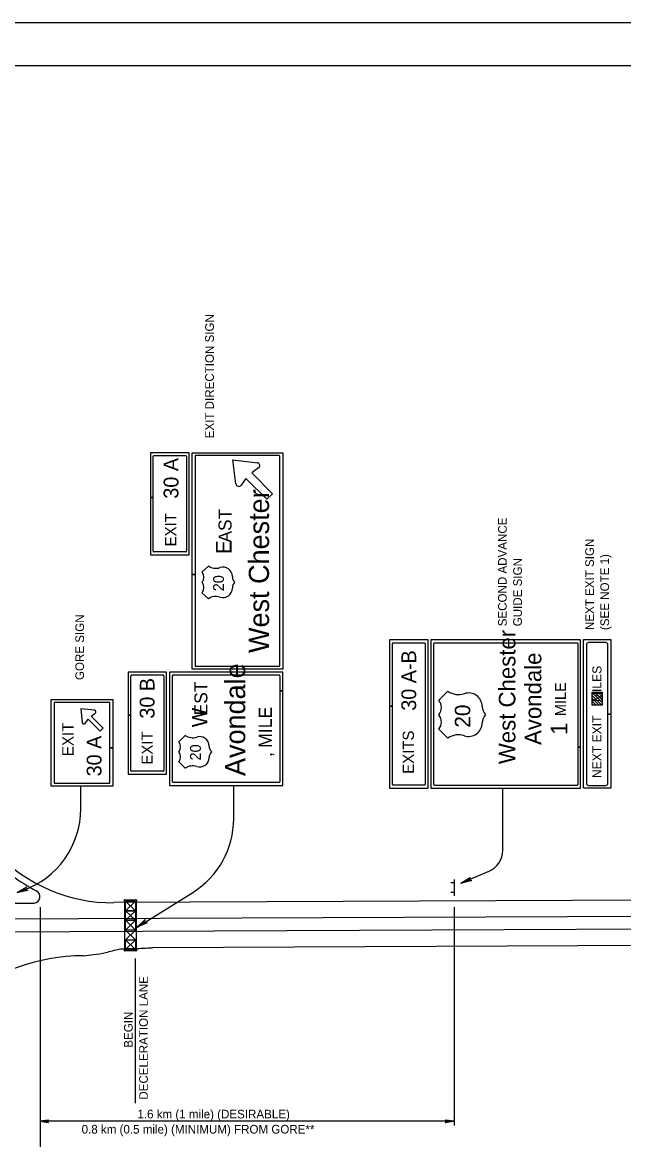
# Model space of a CAD drawing. Extents: x 640994 to 644422, y 298458 to 299646.
# Drawn here: x 643942.6 to 644151, y 299258.5 to 299645.6 of the extents above; entities that cross this region are included whole.
import ezdxf

# ---------------------------------------------------------------- set-up
doc = ezdxf.new("R2010")
doc.units = 0
for name, color, linetype in [('1', 7, 'Continuous'), ('2', 7, 'Continuous'), ('XCS-GRID-MIN', 7, 'Continuous')]:
    doc.layers.add(name, color=color, linetype=linetype)

msp = doc.modelspace()

# ---------------------------------------------------------------- linework, layer by layer
at = {"layer": '1'}
msp.add_line((643557.31, 299630.63), (644343.31, 299630.63), dxfattribs=at)
at = {"layer": '2'}
for p, q in [((644000.44, 299496.52), (643986.94, 299496.52)), ((643986.94, 299496.52), (643986.94, 299480.97)), ((643987.94, 299480.97), (643987.94, 299495.27)), ((643988.19, 299495.52), (643999.19, 299495.52)), ((643999.44, 299495.27), (643999.44, 299462.39)), ((644000.44, 299461.14), (644000.44, 299496.52)), ((644001.44, 299454.33), (644001.44, 299496.52)), ((644001.44, 299496.52), (644032.81, 299496.52)), ((644031.56, 299495.52), (644002.44, 299495.52)), ((644002.44, 299495.52), (644002.44, 299454.33)), ((644016.56, 299485.77), (644015.56, 299494.02)), ((644015.56, 299494.02), (644024.06, 299493.02)), ((644031.81, 299422.77), (644031.81, 299495.27)), ((644032.81, 299496.52), (644032.81, 299421.52)), ((644024.44, 299491.27), (644022.06, 299489.52)), ((644022.06, 299489.52), (644029.31, 299482.27)), ((644020.06, 299487.64), (644018.44, 299485.27)), ((644027.31, 299480.39), (644020.06, 299487.64)), ((644029.31, 299482.27), (644027.31, 299480.39)), ((643987.94, 299480.97), (643986.94, 299480.97)), ((643986.94, 299480.97), (643986.94, 299461.14)), ((643986.94, 299480.97), (643987.94, 299480.97)), ((643987.94, 299462.39), (643987.94, 299480.97)), ((643999.19, 299462.14), (643988.19, 299462.14)), ((643986.94, 299461.14), (644000.44, 299461.14)), ((644004.81, 299455.14), (644007.06, 299457.27)), ((644012.19, 299456.89), (644012.19, 299456.89)), ((644002.44, 299454.33), (644001.44, 299454.33)), ((644001.44, 299421.52), (644001.44, 299454.33)), ((644001.44, 299454.33), (644002.44, 299454.33)), ((644002.44, 299454.33), (644002.44, 299422.77)), ((644010.56, 299451.64), (644010.56, 299451.64)), ((644010.56, 299451.64), (644010.56, 299451.64)), ((644010.56, 299451.64), (644010.56, 299451.64)), ((644010.56, 299451.64), (644010.56, 299451.64)), ((644010.56, 299451.64), (644010.56, 299451.64)), ((644010.56, 299451.64), (644010.56, 299451.64)), ((644012.81, 299453.89), (644012.81, 299453.89)), ((644015.31, 299453.52), (644015.31, 299453.52)), ((644007.06, 299445.89), (644004.81, 299448.02)), ((644015.31, 299449.64), (644015.31, 299449.64)), ((644083.19, 299431.64), (644069.81, 299431.64)), ((644069.81, 299431.64), (644069.81, 299408.72)), ((644083.19, 299380.36), (644083.19, 299431.64)), ((644136.06, 299431.64), (644084.19, 299431.64)), ((644084.19, 299431.64), (644084.19, 299380.27)), ((644136.06, 299394.53), (644136.06, 299431.64)), ((644137.06, 299380.27), (644137.06, 299431.77)), ((644137.06, 299431.77), (644146.5, 299431.77)), ((644146.5, 299431.77), (644146.5, 299405.98)), ((644070.81, 299408.72), (644070.81, 299430.39)), ((644071.06, 299430.64), (644081.94, 299430.64)), ((644082.19, 299430.39), (644082.19, 299381.61)), ((644085.19, 299381.52), (644085.19, 299430.39)), ((644085.44, 299430.64), (644134.81, 299430.64)), ((644135.06, 299430.39), (644135.06, 299394.53)), ((644138.06, 299430.02), (644138.06, 299382.02)), ((644144.75, 299430.77), (644138.81, 299430.77)), ((644145.5, 299405.98), (644145.5, 299430.02)), ((643992.56, 299420.52), (643979.19, 299420.52)), ((643979.19, 299420.52), (643979.19, 299405.6)), ((643992.56, 299385.14), (643992.56, 299420.52)), ((644032.81, 299420.52), (643993.56, 299420.52)), ((643993.56, 299420.52), (643993.56, 299381.27)), ((644032.81, 299421.52), (644001.44, 299421.52)), ((644002.69, 299422.52), (644031.56, 299422.52)), ((644032.81, 299414), (644032.81, 299420.52)), ((643980.19, 299405.6), (643980.19, 299419.27)), ((643980.44, 299419.52), (643991.31, 299419.52)), ((643991.56, 299419.27), (643991.56, 299386.39)), ((643994.56, 299382.52), (643994.56, 299419.27)), ((643994.81, 299419.52), (644031.56, 299419.52)), ((644031.81, 299419.27), (644031.81, 299414)), ((644031.81, 299414), (644032.81, 299414)), ((644032.81, 299414), (644031.81, 299414)), ((644031.81, 299414), (644031.81, 299382.52)), ((644032.81, 299381.27), (644032.81, 299414)), ((644086.94, 299410.77), (644090.06, 299413.89)), ((644097.19, 299413.27), (644097.19, 299413.27)), ((644143.56, 299409.95), (644140.01, 299413.5)), ((644143.41, 299409.04), (644140.01, 299412.44)), ((644143.56, 299410.92), (644140.96, 299413.52)), ((644143.56, 299411.94), (644141.97, 299413.52)), ((644143.56, 299412.91), (644142.95, 299413.52)), ((643952.56, 299381.02), (643952.56, 299411.02)), ((643952.56, 299411.02), (643973.94, 299411.02)), ((643953.56, 299409.77), (643953.56, 299382.27)), ((643972.69, 299410.02), (643953.81, 299410.02)), ((643972.94, 299394.23), (643972.94, 299409.77)), ((643973.94, 299411.02), (643973.94, 299394.23)), ((644070.81, 299408.72), (644069.81, 299408.72)), ((644069.81, 299408.72), (644069.81, 299380.36)), ((644069.81, 299408.72), (644070.81, 299408.72)), ((644070.81, 299381.61), (644070.81, 299408.72)), ((644101.94, 299408.64), (644101.94, 299408.64)), ((644142.44, 299409.04), (644140.01, 299411.47)), ((644141.42, 299409.04), (644140.01, 299410.45)), ((644140.49, 299409.04), (644140.01, 299409.52)), ((643967.59, 299407.28), (643962.79, 299407.82)), ((643962.79, 299407.82), (643963.33, 299403.02)), ((643964.33, 299402.75), (643965.38, 299404.17)), ((643965.38, 299404.17), (643969.5, 299400.04)), ((643966.44, 299405.23), (643967.86, 299406.28)), ((643970.57, 299401.11), (643966.44, 299405.23)), ((643980.19, 299405.6), (643979.19, 299405.6)), ((643979.19, 299405.6), (643979.19, 299385.14)), ((643979.19, 299405.6), (643980.19, 299405.6)), ((643980.19, 299386.39), (643980.19, 299405.6)), ((644095.19, 299405.77), (644095.19, 299405.77)), ((644095.19, 299405.77), (644095.19, 299405.77)), ((644146.5, 299405.98), (644145.5, 299405.98)), ((644145.5, 299382.02), (644145.5, 299405.98)), ((644145.5, 299405.98), (644146.5, 299405.98)), ((644146.5, 299405.98), (644146.5, 299380.27)), ((643969.5, 299400.04), (643970.57, 299401.11)), ((644090.06, 299397.64), (644086.94, 299400.77)), ((644101.94, 299402.89), (644101.94, 299402.89)), ((643996.81, 299396.39), (643999.06, 299398.64)), ((644004.06, 299398.14), (644004.06, 299398.14)), ((643972.94, 299394.23), (643973.94, 299394.23)), ((643973.94, 299394.23), (643972.94, 299394.23)), ((643972.94, 299382.27), (643972.94, 299394.23)), ((643973.94, 299394.23), (643973.94, 299381.02)), ((644002.56, 299392.89), (644002.56, 299392.89)), ((644002.56, 299392.89), (644002.56, 299392.89)), ((644002.56, 299392.89), (644002.56, 299392.89)), ((644002.56, 299392.89), (644002.56, 299392.89)), ((644007.31, 299394.89), (644007.31, 299394.89)), ((644136.06, 299394.53), (644135.06, 299394.53)), ((644135.06, 299394.53), (644135.06, 299381.52)), ((644135.06, 299394.53), (644136.06, 299394.53)), ((644136.06, 299380.27), (644136.06, 299394.53)), ((643999.06, 299387.14), (643996.81, 299389.39)), ((644007.31, 299390.89), (644007.31, 299390.89)), ((643979.19, 299385.14), (643992.56, 299385.14)), ((643991.31, 299386.14), (643980.44, 299386.14)), ((643973.94, 299381.02), (643952.56, 299381.02)), ((643953.81, 299382.02), (643972.69, 299382.02)), ((643962.81, 299373.17), (643962.81, 299381.02)), ((643993.56, 299381.27), (644032.81, 299381.27)), ((644031.56, 299382.27), (643994.81, 299382.27)), ((644015.81, 299369.66), (644015.81, 299381.27)), ((644081.94, 299381.36), (644071.06, 299381.36)), ((644134.81, 299381.27), (644085.44, 299381.27)), ((644138.81, 299381.27), (644144.75, 299381.27)), ((644069.81, 299380.36), (644083.19, 299380.36)), ((644084.19, 299380.27), (644136.06, 299380.27)), ((644109.06, 299358.77), (644109.06, 299380.27)), ((644146.5, 299380.27), (644137.06, 299380.27)), ((644094.56, 299347.39), (644104.06, 299351.39)), ((644092.19, 299347.52), (644091.06, 299347.52)), ((644092.19, 299348.64), (644092.19, 299343.02)), ((644343.31, 299342.27), (643974.31, 299340.64)), ((643982.31, 299332.14), (644001.67, 299344.19)), ((644092.19, 299344.14), (644091.06, 299344.14)), ((643946.69, 299340.39), (643886.06, 299340.27)), ((643948.69, 299339.02), (643948.69, 299263.39)), ((643978.31, 299341.14), (643981.81, 299337.77)), ((643981.81, 299341.14), (643978.31, 299337.77)), ((644092.19, 299339.02), (644092.19, 299263.39)), ((644343.31, 299336.65), (643825.94, 299334.39)), ((643978.31, 299337.77), (643981.81, 299334.52)), ((643981.81, 299337.77), (643978.31, 299334.52)), ((643978.31, 299334.52), (643981.81, 299331.14)), ((643981.81, 299334.52), (643978.31, 299331.14)), ((644343.31, 299332.27), (643825.19, 299329.89)), ((643978.31, 299331.14), (643981.81, 299327.77)), ((643981.81, 299331.14), (643978.31, 299327.77)), ((643980.06, 299332.77), (643980.06, 299332.77)), ((643978.31, 299327.77), (643981.81, 299324.39)), ((643981.81, 299327.77), (643978.31, 299324.39)), ((644343.31, 299326.65), (643987.69, 299325.02)), ((643981.81, 299324.39), (643981.81, 299324.39)), ((643981.69, 299321.27), (643981.69, 299271.14)), ((643948.69, 299311.52), (643948.69, 299236.52)), ((644092.19, 299264.89), (643948.69, 299264.89))]:
    msp.add_line(p, q, dxfattribs=at)
for points in [[(644143.56, 299409.04), (644140.01, 299409.04), (644140.01, 299413.52), (644143.56, 299413.52)], [(643978.31, 299337.77), (643978.31, 299341.14), (643981.81, 299341.14), (643981.81, 299337.77)], [(643978.31, 299334.52), (643978.31, 299337.77), (643981.81, 299337.77), (643981.81, 299334.52)], [(643978.31, 299331.14), (643978.31, 299334.52), (643981.81, 299334.52), (643981.81, 299331.14)], [(643978.31, 299324.39), (643978.31, 299327.77), (643981.81, 299327.77), (643981.81, 299324.39)]]:
    msp.add_lwpolyline(points, close=True, dxfattribs=at)
for points in [[(643944.1, 299344.97), (643944.08, 299345.22), (643940.78, 299344.11), (643944.1, 299344.97), (643944.48, 299344.87), (643940.78, 299344.11), (643943.68, 299345.57), (643943.91, 299345.84), (643940.78, 299344.11), (643944.15, 299346.1), (643943.91, 299345.84)], [(644097.94, 299348.27), (644097.81, 299348.52), (644094.56, 299347.39), (644097.94, 299348.27), (644098.31, 299348.27), (644094.56, 299347.39), (644097.56, 299348.89), (644097.69, 299349.14), (644094.56, 299347.39), (644097.81, 299349.39), (644097.69, 299349.14)], [(643977.94, 299341.14), (643977.94, 299324.02)], [(643981.81, 299341.52), (643978.31, 299341.52)], [(643982.19, 299324.02), (643982.19, 299341.14)], [(643985.44, 299333.64), (643985.31, 299333.89), (643982.31, 299332.14), (643985.44, 299333.64), (643985.81, 299333.64), (643982.31, 299332.14), (643984.94, 299334.14), (643985.06, 299334.39), (643982.31, 299332.14), (643985.19, 299334.77), (643985.06, 299334.39)], [(643978.31, 299324.02), (643981.81, 299324.02)], [(643951.54, 299264.53), (643951.43, 299264.74), (643948.69, 299264.89), (643951.54, 299264.53), (643951.69, 299264.41), (643948.69, 299264.89), (643951.43, 299265.03), (643951.53, 299265.23), (643948.69, 299264.89), (643951.69, 299265.37), (643951.53, 299265.23)], [(644089.33, 299265.25), (644089.44, 299265.04), (644092.19, 299264.89), (644089.33, 299265.25), (644089.19, 299265.37), (644092.19, 299264.89), (644089.44, 299264.76), (644089.34, 299264.55), (644092.19, 299264.89), (644089.19, 299264.41), (644089.34, 299264.55)]]:
    msp.add_lwpolyline(points, dxfattribs=at)
for centre in [(643978.17, 299341.38), (643981.96, 299341.38), (643978.17, 299324.16), (643981.96, 299324.16)]:
    msp.add_circle(centre, 0.301, dxfattribs=at)
for centre, radius, start, end in [((643988.19, 299495.27), 0.25, 90, 180), ((643999.19, 299495.27), 0.25, 0, 90), ((644002.69, 299495.27), 0.25, 90, 180), ((644031.56, 299495.27), 0.25, 0, 90), ((644023.88, 299492.06), 0.978, 303.2449, 87.1516), ((644017.58, 299485.83), 0.978, 184.8565, 325.522), ((643988.19, 299462.39), 0.25, 180, 270), ((643999.19, 299462.39), 0.25, 270, 0), ((644002.53, 299453.37), 2.93, 323.136, 36.864), ((644009.63, 299461.03), 4.55, 235.4253, 288.1711), ((644012.09, 299453.62), 3.26, 0.0047, 108.548), ((644002.53, 299449.86), 2.93, 323.136, 36.864), ((644018.11, 299453.62), 2.76, 180, 226.2725), ((644018.11, 299449.61), 2.76, 133.7275, 180), ((644009.63, 299442.19), 4.55, 71.8289, 124.5747), ((644012.09, 299449.61), 3.26, 251.452, 359.9953), ((644071.06, 299430.39), 0.25, 90, 180), ((644081.94, 299430.39), 0.25, 0, 90), ((644085.44, 299430.39), 0.25, 90, 180), ((644134.81, 299430.39), 0.25, 0, 90), ((644138.81, 299430.02), 0.75, 90, 180), ((644144.75, 299430.02), 0.75, 0, 90), ((644002.69, 299422.77), 0.25, 180, 270), ((644031.56, 299422.77), 0.25, 270, 0), ((643980.44, 299419.27), 0.25, 90, 180), ((643991.31, 299419.27), 0.25, 0, 90), ((643994.81, 299419.27), 0.25, 90, 180), ((644031.56, 299419.27), 0.25, 0, 90), ((644093.74, 299419.22), 6.5, 235.4253, 288.1711), ((644097.25, 299408.62), 4.66, 0.0047, 108.548), ((643953.81, 299409.77), 0.25, 90, 180), ((643972.69, 299409.77), 0.25, 0, 90), ((644083.6, 299408.26), 4.18, 323.136, 36.864), ((644105.85, 299408.62), 3.94, 180, 226.2725), ((643967.52, 299406.73), 0.559, 306.5527, 83.5801), ((644083.6, 299403.25), 4.18, 323.136, 36.864), ((644105.85, 299402.89), 3.94, 133.7275, 180), ((643963.88, 299403.09), 0.559, 186.4218, 323.4493), ((644097.25, 299402.89), 4.66, 251.452, 359.9953), ((643994.48, 299394.65), 2.93, 323.136, 36.864), ((644001.57, 299402.32), 4.55, 235.4253, 288.1711), ((644004.03, 299394.9), 3.26, 0.0047, 108.548), ((644093.74, 299392.3), 6.5, 71.8289, 124.5747), ((643994.48, 299391.14), 2.93, 323.136, 36.864), ((644010.05, 299394.9), 2.76, 180, 226.2725), ((644010.05, 299390.89), 2.76, 133.7275, 180), ((644004.03, 299390.89), 3.26, 251.452, 359.9953), ((643980.44, 299386.39), 0.25, 180, 270), ((643991.31, 299386.39), 0.25, 270, 0), ((644001.57, 299383.47), 4.55, 71.8289, 124.5747), ((643953.81, 299382.27), 0.25, 180, 270), ((643972.69, 299382.27), 0.25, 270, 0), ((643994.81, 299382.52), 0.25, 180, 270), ((644031.56, 299382.52), 0.25, 270, 0), ((644071.06, 299381.61), 0.25, 180, 270), ((644081.94, 299381.61), 0.25, 270, 0), ((644085.44, 299381.52), 0.25, 180, 270), ((644134.81, 299381.52), 0.25, 270, 0), ((644138.81, 299382.02), 0.75, 180, 270), ((644144.75, 299382.02), 0.75, 270, 0), ((643932.81, 299373.17), 30, 289.3407, 0), ((643985.81, 299369.66), 30, 301.9022, 0), ((643974, 299396.57), 55.99, 223.3194, 270.2525), ((644101.06, 299358.82), 8, 292.4631, 0), ((643974, 299396.57), 58.23, 223.3194, 242.7882), ((643946.34, 299342.74), 2.3, 278.0002, 63.1291), ((643963.94, 299255.09), 67.18, 90.2526, 130)]:
    msp.add_arc(centre, radius, start, end, dxfattribs=at)
msp.add_spline([(643963.69, 299322.27), (643967.19, 299322.64), (643971.56, 299323.39), (643976.06, 299324.52), (643981.31, 299324.77), (643987.69, 299325.02)], degree=3, dxfattribs=at)
at = {"layer": 'XCS-GRID-MIN'}
msp.add_lwpolyline([(643517.31, 299645.63), (644358.31, 299645.63), (644358.31, 299051.63), (643517.31, 299051.63)], close=True, dxfattribs=at)

# ---------------------------------------------------------------- texts
at = {"layer": '2'}
for s, height, rotation, p in [('EXIT DIRECTION SIGN', 3, 90, (644008.94, 299501.52)), ('30 A', 5.125, 90, (643996.66, 299480.6)), ('West Chester', 6.9997, 89.9998, (644028.06, 299427.14)), ('EXIT', 3.875, 90, (643995.93, 299464.06)), ('AST', 4.5, 90, (644015.06, 299465.39)), ('SECOND ADVANCE', 3, 90, (644110.44, 299436.39)), ('NEXT EXIT SIGN', 3, 90, (644140.66, 299435.09)), ('E', 5.38, 90, (644015.06, 299461.39)), ('GUIDE SIGN', 3, 90, (644115.69, 299436.39)), ('(SEE NOTE 1)', 3, 90, (644145.91, 299435.09)), ('20', 3.75, 90, (644012.44, 299448.52)), ('GORE SIGN', 3, 90, (643963.94, 299417.77)), ('West Chester', 5.7435, 90, (644113.44, 299388.64)), ('30 A-B', 5.125, 90, (644079.06, 299407.13)), ('Avondale', 5.743, 90, (644122.44, 299395.27)), ('Avondale', 7, 90, (644019.81, 299384.52)), ('NEXT EXIT    MILES', 3.1343, 90, (644143.27, 299383.81)), ('30 B', 5.125, 90, (643988.38, 299404.39)), ('EST', 4.5, 90, (644006.69, 299405.52)), ('MILE', 3.749, 90, (644130.94, 299405.27)), ('MILE', 3.749, 90, (644130.94, 299405.27)), ('W', 5.38, 90, (644006.69, 299401.39)), ('‚ MILE', 4.546, 90, (644029.06, 299391.27)), ('20', 5.375, 90, (644097.81, 299401.27)), ('EXIT', 3.917, 90, (643960.31, 299391.39)), ('1', 5.74, 90, (644131.44, 299398.77)), ('30 A', 5.125, 90, (643970, 299384.38)), ('EXIT', 3.875, 90, (643987.76, 299388.46)), ('EXITS', 3.875, 90, (644078.27, 299385.29)), ('20', 3.75, 90, (644004.44, 299389.89)), ('DECELERATION LANE', 3, 90, (643986.06, 299272.39)), ('BEGIN', 3, 90, (643980.81, 299290.39))]:
    msp.add_text(s, height=height, rotation=rotation, dxfattribs=at).set_placement(p)
for s, p in [('1.6 km (1 mile) (DESIRABLE)', (643982.45, 299265.89)), (' 0.8 km (0.5 mile) (MINIMUM) FROM GORE**', (643962, 299260.64))]:
    msp.add_text(s, height=3, dxfattribs=at).set_placement(p)

doc.saveas('drawing.dxf')
